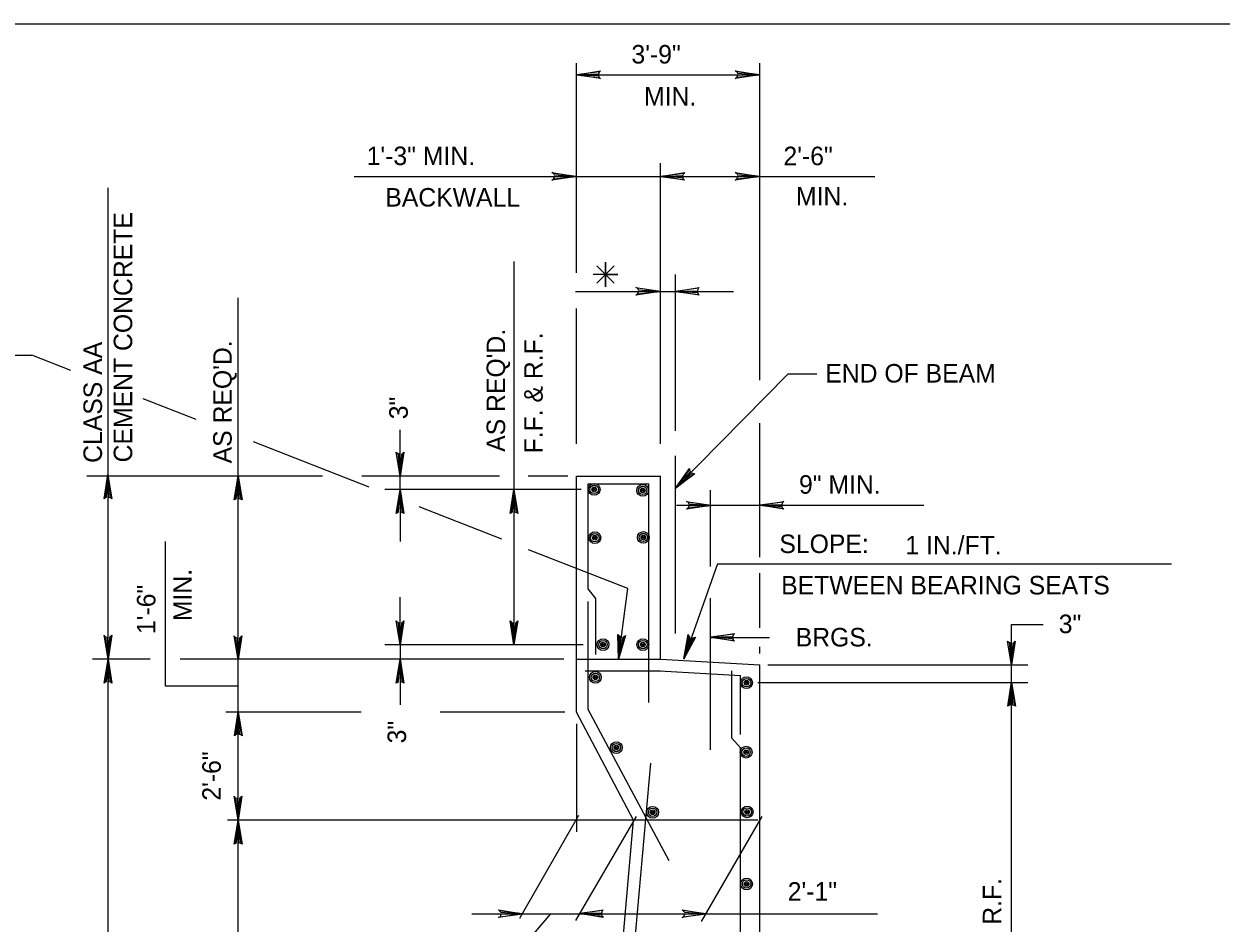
# Model space of a CAD drawing. Extents: x 235 to 2276, y 116 to 1308.
# Drawn here: x 807.5 to 1001.6, y 549.7 to 695.4 of the extents above; entities that cross this region are included whole.
import ezdxf

# ---------------------------------------------------------------- set-up
doc = ezdxf.new("R2010")
doc.units = 0
doc.layers.add('1', color=7, linetype='Continuous')

msp = doc.modelspace()

# ---------------------------------------------------------------- linework, layer by layer
at = {"layer": '1'}
for p, q in [((619.42, 695.41), (1405.42, 695.41)), ((897.11, 655.1), (897.11, 689.06)), ((926.83, 637.7), (926.83, 689.06)), ((897.11, 687.18), (926.83, 687.18)), ((910.74, 627.35), (910.74, 672.83)), ((861.07, 670.7), (945.46, 670.7)), ((821.17, 619.49), (821.17, 668.86)), ((886.97, 656.9), (886.97, 629.49)), ((901.82, 654.82), (901.82, 654.82)), ((913.14, 629.49), (913.14, 654.82)), ((896.96, 652.07), (922.56, 652.07)), ((842.27, 628.09), (842.27, 651.02)), ((897.11, 627.35), (897.11, 649.32)), ((763.08, 641.72), (808.83, 641.72)), ((815.13, 639.25), (808.83, 641.72)), ((913.14, 620.19), (931.41, 638.7)), ((931.41, 638.7), (936.05, 638.7)), ((835.46, 631.3), (826.89, 634.65)), ((926.83, 609.02), (926.83, 630.71)), ((868.52, 619.96), (868.52, 629.65)), ((886.97, 629.49), (886.97, 617.93)), ((842.27, 622.15), (842.27, 628.09)), ((863.5, 620.32), (844.73, 627.67)), ((913.14, 596.62), (913.14, 625.41)), ((839.14, 622.15), (817.74, 622.15)), ((821.17, 592.46), (821.17, 622.15)), ((855.95, 622.15), (839.14, 622.15)), ((842.27, 592.46), (842.27, 622.15)), ((884.63, 622.15), (862.31, 622.15)), ((895.7, 622.15), (889.27, 622.15)), ((897.11, 583.87), (897.11, 622.15)), ((897.11, 622.15), (910.74, 622.15)), ((910.74, 592.46), (910.74, 622.15)), ((897.89, 619.96), (866.02, 619.96)), ((868.52, 619.96), (868.52, 611.52)), ((886.97, 619.96), (886.97, 594.81)), ((898.99, 620.9), (908.83, 620.9)), ((898.99, 603.87), (898.99, 620.9)), ((908.83, 585.43), (908.83, 620.9)), ((918.86, 607.49), (918.86, 619.84)), ((885.03, 611.9), (871.62, 617.15)), ((913.34, 617.42), (953.41, 617.42)), ((830.49, 588.09), (830.49, 611.56)), ((905.44, 603.91), (889.35, 610.21)), ((919.96, 607.93), (993.58, 607.93)), ((919.96, 607.93), (993.17, 607.93)), ((926.83, 597.55), (926.83, 606.43)), ((900.24, 602.31), (898.99, 603.87)), ((903.93, 592.46), (905.44, 603.91)), ((868.52, 594.81), (868.52, 602.51)), ((898.99, 584.34), (898.99, 601.84)), ((900.24, 593.24), (900.24, 602.31)), ((918.86, 577.78), (918.86, 602.33)), ((967.61, 598.07), (972.75, 598.07)), ((967.61, 588.71), (967.61, 598.07)), ((918.86, 596), (928.4, 596)), ((898.2, 594.81), (866.02, 594.81)), ((868.52, 594.81), (868.52, 585.07)), ((926.83, 593.4), (926.83, 594.46)), ((827.98, 592.46), (818.67, 592.46)), ((821.17, 453.24), (821.17, 592.46)), ((895.08, 592.46), (832.87, 592.46)), ((842.27, 583.87), (842.27, 592.46)), ((897.11, 592.46), (910.74, 592.46)), ((910.74, 592.46), (926.83, 591.53)), ((898.54, 590.59), (910.74, 590.59)), ((910.58, 590.59), (923.71, 589.81)), ((922.3, 579.65), (922.3, 590.59)), ((926.83, 474.49), (926.83, 591.53)), ((928.13, 591.53), (970.27, 591.53)), ((842.27, 588.09), (830.49, 588.09)), ((923.71, 580.28), (923.71, 589.81)), ((926.52, 588.71), (970.27, 588.71)), ((967.61, 477.15), (967.61, 588.71)), ((912.11, 559.81), (898.99, 584.34)), ((862.2, 583.87), (840.28, 583.87)), ((842.27, 474.49), (842.27, 583.87)), ((895.24, 583.87), (875.03, 583.87)), ((906.33, 566.37), (897.11, 583.87)), ((897.11, 581.99), (897.11, 564.49)), ((923.71, 578.09), (922.3, 579.65)), ((923.71, 537.57), (923.71, 578.09)), ((901.8, 493.09), (909.14, 575.59)), ((897.42, 567.15), (887.89, 550.43)), ((906.8, 566.99), (896.95, 550.12)), ((927.15, 566.99), (917.3, 549.96)), ((926.49, 566.37), (840.55, 566.37)), ((898.36, 474.49), (906.33, 566.37)), ((892.89, 551.21), (876.95, 532.46)), ((880.17, 551.21), (897.58, 551.21)), ((897.58, 551.21), (916.02, 551.21)), ((918.08, 551.21), (945.89, 551.21))]:
    msp.add_line(p, q, dxfattribs=at)
for points in [[(900.86, 686.68), (900.74, 686.93), (897.11, 687.18), (900.86, 686.68), (900.99, 686.56), (897.11, 687.18), (900.74, 687.31), (900.86, 687.68), (897.11, 687.18), (900.99, 687.81), (900.86, 687.68)], [(923.08, 687.68), (923.21, 687.43), (926.83, 687.18), (923.08, 687.68), (922.83, 687.81), (926.83, 687.18), (923.21, 687.06), (923.08, 686.81), (926.83, 687.18), (922.83, 686.56), (923.08, 686.81)], [(893.36, 671.2), (893.49, 670.95), (897.11, 670.7), (893.36, 671.2), (893.11, 671.33), (897.11, 670.7), (893.49, 670.58), (893.36, 670.33), (897.11, 670.7), (893.11, 670.08), (893.36, 670.33)], [(914.49, 670.2), (914.36, 670.45), (910.74, 670.7), (914.49, 670.2), (914.61, 670.08), (910.74, 670.7), (914.36, 670.83), (914.49, 671.2), (910.74, 670.7), (914.61, 671.33), (914.49, 671.2)], [(923.08, 671.2), (923.21, 670.95), (926.83, 670.7), (923.08, 671.2), (922.83, 671.33), (926.83, 670.7), (923.21, 670.58), (923.08, 670.33), (926.83, 670.7), (922.83, 670.08), (923.08, 670.33)], [(903.23, 656.24), (900.41, 653.41), (901.82, 654.82), (903.23, 653.41), (900.41, 656.24), (901.82, 654.82), (901.82, 656.82), (901.82, 652.82), (901.82, 654.82), (903.82, 654.82), (899.82, 654.82)], [(906.99, 652.57), (907.11, 652.32), (910.74, 652.07), (906.99, 652.57), (906.74, 652.69), (910.74, 652.07), (907.11, 651.94), (906.99, 651.69), (910.74, 652.07), (906.74, 651.44), (906.99, 651.69)], [(916.89, 651.57), (916.76, 651.82), (913.14, 652.07), (916.89, 651.57), (917.01, 651.44), (913.14, 652.07), (916.76, 652.19), (916.89, 652.57), (913.14, 652.07), (917.01, 652.69), (916.89, 652.57)], [(869.02, 625.9), (868.77, 625.65), (868.52, 622.15), (869.02, 625.9), (869.14, 626.03), (868.52, 622.15), (868.39, 625.65), (868.14, 625.78), (868.52, 622.15), (867.89, 626.03), (868.14, 625.78)], [(916.13, 622.51), (915.86, 622.6), (913.14, 620.19), (916.13, 622.51), (916.31, 622.51), (913.14, 620.19), (915.6, 622.86), (915.42, 623.21), (913.14, 620.19), (915.42, 623.39), (915.42, 623.21)], [(820.66, 618.6), (820.91, 618.72), (821.16, 622.35), (820.66, 618.6), (820.53, 618.47), (821.16, 622.35), (821.28, 618.72), (821.66, 618.6), (821.16, 622.35), (821.78, 618.47), (821.66, 618.6)], [(841.76, 618.4), (842.01, 618.53), (842.26, 622.15), (841.76, 618.4), (841.64, 618.28), (842.26, 622.15), (842.39, 618.53), (842.76, 618.4), (842.26, 622.15), (842.89, 618.28), (842.76, 618.4)], [(868.02, 616.21), (868.27, 616.34), (868.52, 619.96), (868.02, 616.21), (867.89, 616.09), (868.52, 619.96), (868.64, 616.34), (869.02, 616.21), (868.52, 619.96), (869.14, 616.09), (869.02, 616.21)], [(886.47, 616.21), (886.72, 616.34), (886.97, 619.96), (886.47, 616.21), (886.34, 616.09), (886.97, 619.96), (887.09, 616.34), (887.47, 616.21), (886.97, 619.96), (887.59, 616.09), (887.47, 616.21)], [(915.2, 617.9), (915.33, 617.65), (918.95, 617.4), (915.2, 617.9), (914.95, 618.02), (918.95, 617.4), (915.33, 617.27), (915.2, 617.02), (918.95, 617.4), (914.95, 616.77), (915.2, 617.02)], [(930.58, 616.92), (930.46, 617.17), (926.83, 617.42), (930.58, 616.92), (930.71, 616.79), (926.83, 617.42), (930.46, 617.54), (930.58, 617.92), (926.83, 617.42), (930.71, 618.04), (930.58, 617.92)], [(919.96, 607.93), (914.49, 592.46)], [(869.02, 598.56), (868.77, 598.31), (868.52, 594.81), (869.02, 598.56), (869.14, 598.68), (868.52, 594.81), (868.39, 598.31), (868.14, 598.43), (868.52, 594.81), (867.89, 598.68), (868.14, 598.43)], [(887.47, 598.56), (887.22, 598.31), (886.97, 594.81), (887.47, 598.56), (887.59, 598.68), (886.97, 594.81), (886.84, 598.31), (886.59, 598.43), (886.97, 594.81), (886.34, 598.68), (886.59, 598.43)], [(821.67, 596.22), (821.42, 595.97), (821.17, 592.47), (821.67, 596.22), (821.8, 596.34), (821.17, 592.47), (821.05, 595.97), (820.67, 596.09), (821.17, 592.47), (820.55, 596.34), (820.67, 596.09)], [(842.74, 596.15), (842.49, 595.9), (842.24, 592.4), (842.74, 596.15), (842.86, 596.27), (842.24, 592.4), (842.11, 595.9), (841.74, 596.02), (842.24, 592.4), (841.61, 596.27), (841.74, 596.02)], [(904.89, 596.15), (904.6, 596.04), (903.93, 592.46), (904.89, 596.15), (905.08, 596.32), (903.93, 592.46), (904.22, 596.09), (903.97, 596.26), (903.93, 592.46), (903.82, 596.48), (903.97, 596.26)], [(916.2, 595.91), (915.9, 595.87), (914.5, 592.51), (916.2, 595.91), (916.42, 596.04), (914.5, 592.51), (915.54, 596), (915.33, 596.21), (914.5, 592.51), (915.23, 596.47), (915.33, 596.21)], [(922.6, 595.51), (922.47, 595.76), (918.85, 596.01), (922.6, 595.51), (922.72, 595.38), (918.85, 596.01), (922.47, 596.13), (922.6, 596.51), (918.85, 596.01), (922.72, 596.63), (922.6, 596.51)], [(968.11, 595.28), (967.86, 595.03), (967.61, 591.53), (968.11, 595.28), (968.24, 595.4), (967.61, 591.53), (967.49, 595.03), (967.24, 595.15), (967.61, 591.53), (966.99, 595.4), (967.24, 595.15)], [(820.68, 588.73), (820.93, 588.85), (821.18, 592.48), (820.68, 588.73), (820.55, 588.6), (821.18, 592.48), (821.3, 588.85), (821.68, 588.73), (821.18, 592.48), (821.8, 588.6), (821.68, 588.73)], [(868.02, 588.71), (868.27, 588.84), (868.52, 592.46), (868.02, 588.71), (867.89, 588.59), (868.52, 592.46), (868.64, 588.84), (869.02, 588.71), (868.52, 592.46), (869.14, 588.59), (869.02, 588.71)], [(967.15, 584.97), (967.4, 585.09), (967.65, 588.72), (967.15, 584.97), (967.03, 584.84), (967.65, 588.72), (967.78, 585.09), (968.15, 584.97), (967.65, 588.72), (968.28, 584.84), (968.15, 584.97)], [(841.78, 580.2), (842.03, 580.32), (842.28, 583.95), (841.78, 580.2), (841.66, 580.07), (842.28, 583.95), (842.41, 580.32), (842.78, 580.2), (842.28, 583.95), (842.91, 580.07), (842.78, 580.2)], [(842.75, 570.13), (842.5, 569.88), (842.25, 566.38), (842.75, 570.13), (842.88, 570.25), (842.25, 566.38), (842.13, 569.88), (841.75, 570), (842.25, 566.38), (841.63, 570.25), (841.75, 570)], [(841.77, 562.62), (842.02, 562.74), (842.27, 566.37), (841.77, 562.62), (841.64, 562.49), (842.27, 566.37), (842.39, 562.74), (842.77, 562.62), (842.27, 566.37), (842.89, 562.49), (842.77, 562.62)], [(884.61, 551.71), (884.86, 551.46), (888.36, 551.21), (884.61, 551.71), (884.49, 551.84), (888.36, 551.21), (884.86, 551.09), (884.74, 550.71), (888.36, 551.21), (884.49, 550.59), (884.74, 550.71)], [(901.33, 550.74), (901.2, 550.99), (897.58, 551.24), (901.33, 550.74), (901.45, 550.62), (897.58, 551.24), (901.2, 551.37), (901.33, 551.74), (897.58, 551.24), (901.45, 551.87), (901.33, 551.74)], [(914.35, 551.72), (914.6, 551.47), (918.1, 551.22), (914.35, 551.72), (914.23, 551.84), (918.1, 551.22), (914.6, 551.09), (914.48, 550.72), (918.1, 551.22), (914.23, 550.59), (914.48, 550.72)]]:
    msp.add_lwpolyline(points, dxfattribs=at)
for centre, radius in [((899.98, 619.98), 0.954), ((899.98, 619.98), 0.681), ((899.98, 619.98), 0.372), ((899.98, 619.98), 0.188), ((899.98, 619.98), 0.0805), ((907.85, 619.82), 0.954), ((907.85, 619.82), 0.681), ((907.85, 619.82), 0.372), ((907.85, 619.82), 0.188), ((907.85, 619.82), 0.0805), ((900.09, 612.15), 0.954), ((900.09, 612.15), 0.681), ((900.09, 612.15), 0.372), ((900.09, 612.15), 0.188), ((900.09, 612.15), 0.0805), ((907.95, 612.2), 0.954), ((907.95, 612.2), 0.681), ((907.95, 612.2), 0.372), ((907.95, 612.2), 0.188), ((907.95, 612.2), 0.0805), ((901.42, 594.83), 0.954), ((907.87, 594.83), 0.954), ((901.42, 594.83), 0.681), ((901.42, 594.83), 0.372), ((901.42, 594.83), 0.188), ((901.42, 594.83), 0.0805), ((907.87, 594.83), 0.681), ((907.87, 594.83), 0.372), ((907.87, 594.83), 0.188), ((907.87, 594.83), 0.0805), ((900.18, 589.52), 0.954), ((900.18, 589.52), 0.681), ((900.18, 589.52), 0.372), ((900.18, 589.52), 0.188), ((900.18, 589.52), 0.0805), ((924.67, 588.65), 0.954), ((924.67, 588.65), 0.681), ((924.67, 588.65), 0.372), ((924.67, 588.65), 0.188), ((924.67, 588.65), 0.0805), ((903.57, 578.14), 0.954), ((903.57, 578.14), 0.681), ((903.57, 578.14), 0.372), ((903.57, 578.14), 0.188), ((924.61, 577.4), 0.954), ((903.57, 578.14), 0.0805), ((924.61, 577.4), 0.681), ((924.61, 577.4), 0.372), ((924.61, 577.4), 0.188), ((924.61, 577.4), 0.0805), ((909.45, 567.66), 0.954), ((924.78, 567.72), 0.954), ((909.45, 567.66), 0.681), ((909.45, 567.66), 0.372), ((909.45, 567.66), 0.188), ((909.45, 567.66), 0.0805), ((924.78, 567.72), 0.681), ((924.78, 567.72), 0.372), ((924.78, 567.72), 0.188), ((924.78, 567.72), 0.0805), ((924.68, 556.04), 0.954), ((924.68, 556.04), 0.681), ((924.68, 556.04), 0.372), ((924.68, 556.04), 0.188), ((924.68, 556.04), 0.0805)]:
    msp.add_circle(centre, radius, dxfattribs=at)

# ---------------------------------------------------------------- texts
for s, height, p in [('3\'-9"', 3.003, (906.02, 689)), ('MIN.', 3, (908.06, 682.19)), ('1\'-3" MIN.', 3.003, (863.09, 672.54)), ('2\'-6"', 3.003, (930.66, 672.52)), ('BACKWALL', 3, (866.12, 665.82)), ('MIN.', 3, (932.69, 666)), ('END OF BEAM', 3, (937.44, 637.3)), ('9" MIN.', 3.003, (933.18, 619.28)), ('SLOPE:', 3, (930, 609.67)), ('1 IN./FT.', 3.003, (950.42, 609.44)), ('BETWEEN BEARING SEATS', 3, (930.29, 602.96)), ('3"', 3.003, (975.29, 596.69)), ('  BRGS.', 3, (930.42, 594.53)), ('2\'-1"', 3.003, (931.35, 553.33))]:
    msp.add_text(s, height=height, dxfattribs=at).set_placement(p)
for s, p in [('CEMENT CONCRETE', (825.09, 624.36)), ("AS REQ'D.", (885.54, 626.07)), ('F.F. & R.F.', (891.63, 625.81)), ('CLASS AA', (820.19, 624.28)), ("AS REQ'D.", (841.22, 624.2)), ('3"', (869.76, 631.35)), ('MIN.', (834.73, 598.63)), ('1\'-6"', (828.85, 596.54)), ('3"', (869.48, 578.82)), ('2\'-6"', (839.45, 569.54)), ("AS REQ'D.-F.F.& R.F.", (965.98, 517.24))]:
    msp.add_text(s, height=3, rotation=90, dxfattribs=at).set_placement(p)

doc.saveas('drawing.dxf')
